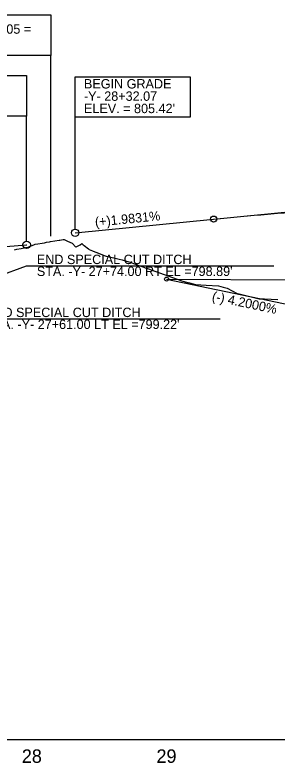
# Model space of a CAD drawing. Extents: x 579185 to 595036, y -53221 to -44640.
# Drawn here: x 581114 to 581308, y -47238 to -46681 of the extents above; entities that cross this region are included whole.
import ezdxf

# ---------------------------------------------------------------- set-up
doc = ezdxf.new("R2010")
doc.units = 0
for name, color, linetype in [('Exist Profile Cell', 7, 'Continuous'), ('Exist Vertical Profile Ground Line', 7, 'Continuous'), ('Exist Vertical Profile Horizontal Axis Label Major', 7, 'Continuous'), ('Prop Grid Mask', 7, 'Continuous'), ('Prop Vertical Profile Curve Label', 7, 'Continuous'), ('Prop Vertical Profile Ditch Grade Left Label', 7, 'Continuous'), ('Prop Vertical Profile Ditch Grade Right', 7, 'Continuous'), ('Prop Vertical Profile Ditch Grade Right Label', 7, 'Continuous'), ('Prop Vertical Profile Grade', 7, 'Continuous'), ('Prop Vertical Profile Grade Label', 7, 'Continuous'), ('Prop VPI Ditch Grade Right Label', 7, 'Continuous'), ('Prop VPI Label', 7, 'Continuous')]:
    doc.layers.add(name, color=color, linetype=linetype)

msp = doc.modelspace()

# ---------------------------------------------------------------- linework, layer by layer
at = {"layer": 'Exist Profile Cell'}
msp.add_line((579326.24, -47220.55), (584953.7, -47220.55), dxfattribs=at)
at = {"layer": 'Exist Vertical Profile Ground Line'}
msp.add_lwpolyline([(581113.17, -46856.05), (581115.07, -46855.7), (581118.2, -46855.12), (581121.42, -46854.52), (581122.81, -46854.36), (581124.45, -46853.7), (581127.57, -46852.43), (581128.53, -46852.04), (581130.7, -46851.67), (581133.82, -46851.14), (581135.61, -46850.83), (581136.95, -46850.57), (581139.14, -46850.14), (581140.07, -46849.99), (581143.2, -46849.51), (581146.32, -46849.03), (581146.86, -46848.95), (581149.45, -46848.58), (581150.15, -46848.47), (581151.52, -46849.29), (581152.57, -46849.76), (581155.99, -46851.29), (581158.82, -46854.19), (581159.13, -46854.03), (581161.95, -46852.32), (581163.21, -46851.56), (581164.31, -46852.43), (581165.07, -46853.03), (581168.2, -46855.49), (581168.81, -46855.97), (581171.32, -46856.9), (581171.83, -46857.09), (581173.58, -46857.82), (581174.45, -46858.18), (581178.65, -46859.94), (581180.7, -46860.65), (581181.31, -46860.85), (581183.71, -46861.44), (581186.95, -46862.19), (581191.12, -46863.16), (581193.2, -46863.69), (581198.31, -46865), (581199.45, -46865.39), (581200.56, -46865.77), (581205.7, -46867.81), (581208.5, -46868.92), (581209.4, -46869.14), (581210.42, -46869.51), (581212.02, -46870.05), (581218.2, -46872.24), (581224.45, -46874.46), (581230.7, -46876.67), (581234.18, -46877.91), (581236.95, -46879.03), (581237.41, -46879.22), (581242.06, -46880.49), (581243.2, -46880.77), (581247.86, -46881.92), (581255.7, -46882.42), (581264.76, -46882.99), (581268.2, -46883.9), (581271.16, -46884.68), (581278.8, -46888.72), (581280.29, -46889.03), (581295.16, -46892.67), (581299.01, -46892.71), (581308.85, -46893.19)], dxfattribs=at)
at = {"layer": 'Prop Grid Mask'}
for points in [[(581033.97, -46681.32), (581140.29, -46681.32), (581140.29, -46711.51), (581033.97, -46711.51)], [(581036.87, -46726.5), (581122.27, -46726.5), (581122.27, -46756.69), (581036.87, -46756.69)], [(581158.31, -46727.3), (581243.7, -46727.3), (581243.7, -46757.49), (581158.31, -46757.49)]]:
    msp.add_lwpolyline(points, close=True, dxfattribs=at)
at = {"layer": 'Prop Vertical Profile Curve Label'}
for p, q in [((581140.29, -46846.01), (581140.29, -46711.51)), ((581122.27, -46849.45), (581122.27, -46756.69)), ((581158.31, -46840.71), (581158.31, -46757.49))]:
    msp.add_line(p, q, dxfattribs=at)
msp.add_circle((581261.24, -46833.26), 2.25, dxfattribs=at)
at = {"layer": 'Prop Vertical Profile Ditch Grade Left Label'}
msp.add_line((581087.24, -46907.48), (581265.99, -46907.48), dxfattribs=at)
at = {"layer": 'Prop Vertical Profile Ditch Grade Right'}
msp.add_lwpolyline([(581226.24, -46877.95), (581326.24, -46898.95), (581526.24, -46946.95), (581636.24, -46969.5)], dxfattribs=at)
at = {"layer": 'Prop Vertical Profile Ditch Grade Right Label'}
for p, q in [((581100.24, -46876.1), (581122.22, -46868.04)), ((581122.22, -46868.04), (581305.86, -46868.04)), ((581226.24, -46877.95), (581343.07, -46878.75))]:
    msp.add_line(p, q, dxfattribs=at)
at = {"layer": 'Prop Vertical Profile Grade'}
for p, q in [((581158.31, -46843.46), (581261.24, -46833.26)), ((581096.24, -46854.53), (581122.27, -46852.39)), ((581122.27, -46852.39), (581122.3, -46852.38))]:
    msp.add_line(p, q, dxfattribs=at)
msp.add_spline([(581261.24, -46833.26), (581271.24, -46832.28), (581281.24, -46831.34), (581291.24, -46830.43), (581301.24, -46829.56), (581311.24, -46828.71), (581321.24, -46827.9), (581331.24, -46827.13), (581341.24, -46826.38), (581351.24, -46825.67), (581361.24, -46824.99), (581371.24, -46824.35), (581381.24, -46823.74), (581391.24, -46823.16), (581401.24, -46822.61), (581411.24, -46822.1), (581421.24, -46821.62), (581431.24, -46821.17), (581441.24, -46820.76), (581451.24, -46820.38), (581461.24, -46820.03), (581471.24, -46819.71), (581481.24, -46819.43), (581491.24, -46819.18), (581501.24, -46818.97), (581511.24, -46818.78), (581521.24, -46818.63), (581531.24, -46818.52), (581541.24, -46818.43), (581551.24, -46818.38), (581561.24, -46818.36), (581571.24, -46818.38), (581581.24, -46818.43), (581591.24, -46818.51), (581601.24, -46818.62), (581611.24, -46818.77), (581621.24, -46818.95), (581631.24, -46819.16), (581641.24, -46819.41), (581651.24, -46819.69), (581661.24, -46820), (581671.24, -46820.35), (581681.24, -46820.73), (581691.24, -46821.14), (581701.24, -46821.58), (581711.24, -46822.06), (581721.24, -46822.57), (581731.24, -46823.11), (581741.24, -46823.69), (581751.24, -46824.3), (581761.24, -46824.94)], degree=3, dxfattribs=at)
at = {"layer": 'Prop VPI Ditch Grade Right Label'}
msp.add_circle((581226.24, -46877.95), 1.5, dxfattribs=at)
at = {"layer": 'Prop VPI Label'}
msp.add_line((581261.24, -46833.26), (581508.5, -46808.74), dxfattribs=at)
for centre in [(581158.31, -46843.46), (581158.31, -46843.46), (581122.27, -46852.39), (581122.3, -46852.38)]:
    msp.add_circle(centre, 2.75, dxfattribs=at)

# ---------------------------------------------------------------- texts
at = {"layer": 'Exist Vertical Profile Horizontal Axis Label Major'}
for s, p in [('28', (581118.7, -47238.05)), ('29', (581218.75, -47238.05))]:
    msp.add_text(s, height=10, dxfattribs=at).set_placement(p)
at = {"layer": 'Prop Vertical Profile Ditch Grade Left Label'}
for s, p in [('END SPECIAL CUT DITCH', (581092.02, -46906.21)), ("STA. -Y- 27+61.00 LT EL =799.22'", (581092.02, -46915.09))]:
    msp.add_text(s, height=7, dxfattribs=at).set_placement(p)
at = {"layer": 'Prop Vertical Profile Ditch Grade Right'}
for s, p in [('END SPECIAL CUT DITCH', (581129.86, -46866.77)), ("STA. -Y- 27+74.00 RT EL =798.89'", (581129.86, -46875.65))]:
    msp.add_text(s, height=7, dxfattribs=at).set_placement(p)
msp.add_text('(-) 4.2000%', height=7, rotation=348.1402, dxfattribs=at).set_placement((581259.58, -46893.89))
at = {"layer": 'Prop Vertical Profile Grade Label'}
msp.add_text('(+)1.9831%', height=7, rotation=5.6627, dxfattribs=at).set_placement((581173.39, -46838.95))
at = {"layer": 'Prop VPI Label'}
for s, p in [('-Y- STA. 28+14.05 =', (581039.81, -46695.31)), ('BEGIN GRADE', (581164.86, -46736.06)), ('-Y- 28+32.07', (581164.86, -46745.24)), ("ELEV. = 805.42'", (581164.86, -46754.41))]:
    msp.add_text(s, height=7, dxfattribs=at).set_placement(p)

doc.saveas('drawing.dxf')
